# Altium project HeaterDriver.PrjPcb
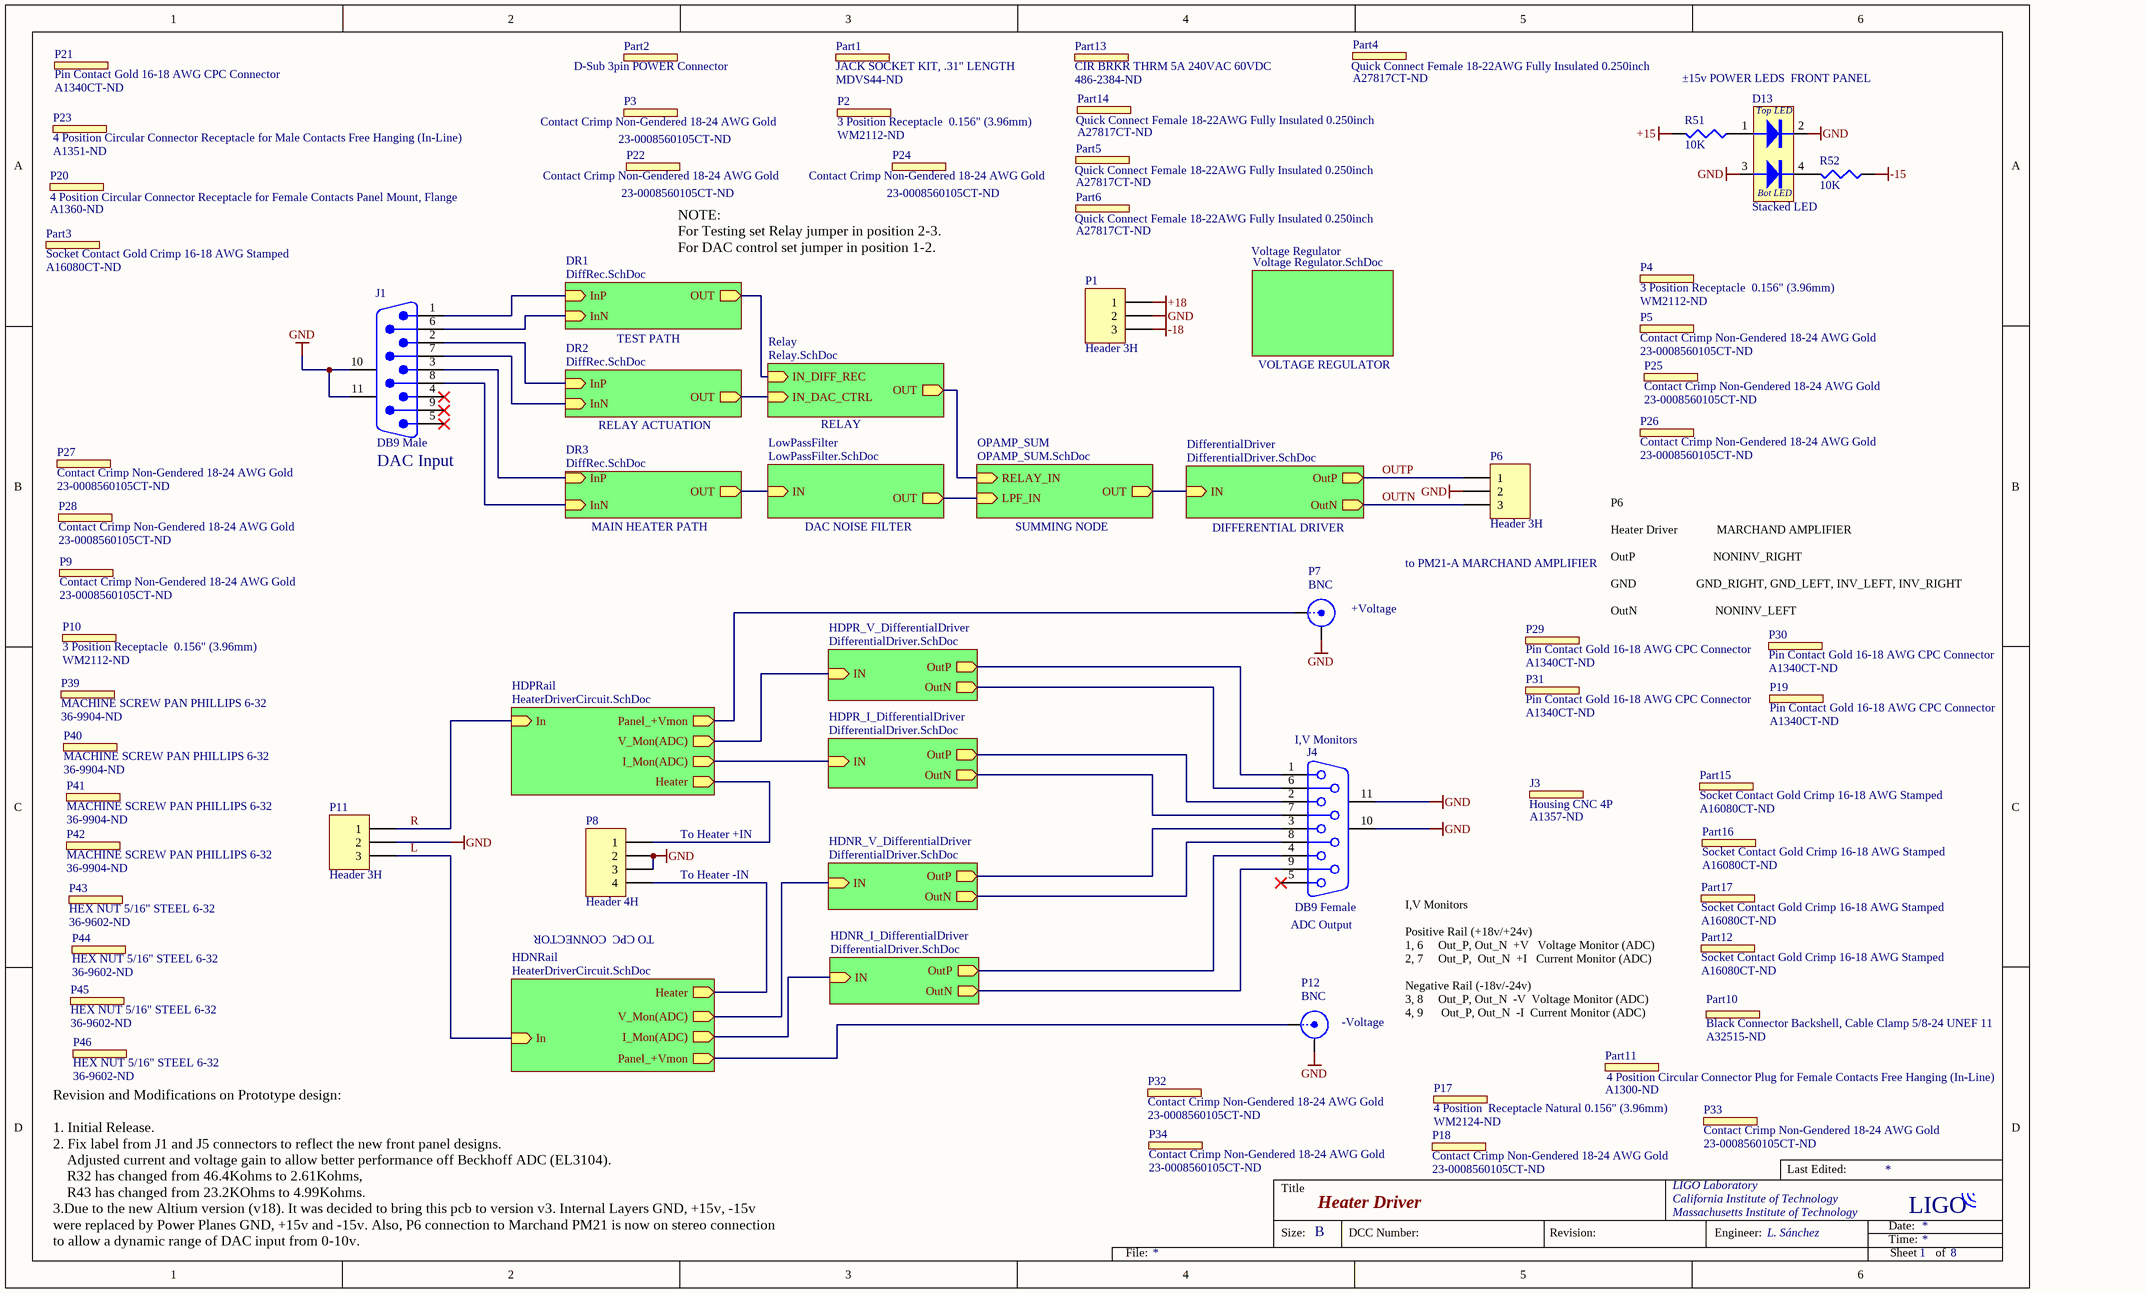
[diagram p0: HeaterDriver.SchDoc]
DCC: D1600454; REV: 3
8 sheets, 332 parts. Net scope: hierarchical (ports join the sheet entries above them; power ports are global).
Board file: HeaterContollerDriver.PcbDoc
Sheets:
  HeaterDriver.SchDoc
    Relay = Relay.SchDoc
    OPAMP_SUM = OPAMP_SUM.SchDoc
    LowPassFilter = LowPassFilter.SchDoc
    DR1 = DiffRec.SchDoc
    DR2 = DiffRec.SchDoc
    DR3 = DiffRec.SchDoc
    HDNR_I_DifferentialDriver = DifferentialDriver.SchDoc
    HDNR_V_DifferentialDriver = DifferentialDriver.SchDoc
    Voltage Regulator = Voltage Regulator.SchDoc
    HDPRail = HeaterDriverCircuit.SchDoc
    HDNRail = HeaterDriverCircuit.SchDoc
    DifferentialDriver = DifferentialDriver.SchDoc
    HDPR_V_DifferentialDriver = DifferentialDriver.SchDoc
    HDPR_I_DifferentialDriver = DifferentialDriver.SchDoc

## Sheet HeaterDriver.SchDoc: Heater Driver
size B; Organization: LIGO Laboratory; Address1: California Institute of Technology; Address2: Massachusetts Institute of Technology; DocumentNumber: D1600454; Revision: 3; SheetNumber: 1; SheetTotal: 8; Engineer: L. Sánchez

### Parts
D13  Stacked LED  [my LUMEX Dual LED]
J1  DB9 Male  [DB9M-RA]
J3  Housing CNC 4P  Digikey Part Number: A1357-ND  (mechanical)
J4  DB9 Female  [DB9F-RA]
P1  Header 3H  [Molex_156_RA_3]
P2  3 Position Receptacle  0.156" (3.96mm)  Digikey Part Number: WM2112-ND  (mechanical)
P3  Contact Crimp Non-Gendered 18-24 AWG Gold  Digikey Part Number: 23-0008560105CT-ND  (mechanical)
P4  3 Position Receptacle  0.156" (3.96mm)  Digikey Part Number: WM2112-ND  (mechanical)
P5  Contact Crimp Non-Gendered 18-24 AWG Gold  Digikey Part Number: 23-0008560105CT-ND  (mechanical)
P6  Header 3H  [Molex_156_RA_3]
P7  BNC  [BNC4]
P8  Header 4H  [Molex_156_RA_4]
P9  Contact Crimp Non-Gendered 18-24 AWG Gold  Digikey Part Number: 23-0008560105CT-ND  (mechanical)
P10  3 Position Receptacle  0.156" (3.96mm)  Digikey Part Number: WM2112-ND  (mechanical)
P11  Header 3H  [Molex_156_RA_3]
P12  BNC  [BNC4]
P17  4 Position  Receptacle Natural 0.156" (3.96mm)  Digikey Part Number: WM2124-ND  (mechanical)
P18  Contact Crimp Non-Gendered 18-24 AWG Gold  Digikey Part Number: 23-0008560105CT-ND  (mechanical)
P19  Pin Contact Gold 16-18 AWG CPC Connector  Digikey Part Number: A1340CT-ND  (mechanical)
P20  4 Position Circular Connector Receptacle for Female Contacts Panel Mount, Flange  Digikey Part Number: A1360-ND  (mechanical)
P21  Pin Contact Gold 16-18 AWG CPC Connector  Digikey Part Number: A1340CT-ND  (mechanical)
P22  Contact Crimp Non-Gendered 18-24 AWG Gold  Digikey Part Number: 23-0008560105CT-ND  (mechanical)
P23  4 Position Circular Connector Receptacle for Male Contacts Free Hanging (In-Line)  Digikey Part Number: A1351-ND  (mechanical)
P24  Contact Crimp Non-Gendered 18-24 AWG Gold  Digikey Part Number: 23-0008560105CT-ND  (mechanical)
P25  Contact Crimp Non-Gendered 18-24 AWG Gold  Digikey Part Number: 23-0008560105CT-ND  (mechanical)
P26  Contact Crimp Non-Gendered 18-24 AWG Gold  Digikey Part Number: 23-0008560105CT-ND  (mechanical)
P27  Contact Crimp Non-Gendered 18-24 AWG Gold  Digikey Part Number: 23-0008560105CT-ND  (mechanical)
P28  Contact Crimp Non-Gendered 18-24 AWG Gold  Digikey Part Number: 23-0008560105CT-ND  (mechanical)
P29  Pin Contact Gold 16-18 AWG CPC Connector  Digikey Part Number: A1340CT-ND  (mechanical)
P30  Pin Contact Gold 16-18 AWG CPC Connector  Digikey Part Number: A1340CT-ND  (mechanical)
P31  Pin Contact Gold 16-18 AWG CPC Connector  Digikey Part Number: A1340CT-ND  (mechanical)
P32  Contact Crimp Non-Gendered 18-24 AWG Gold  Digikey Part Number: 23-0008560105CT-ND  (mechanical)
P33  Contact Crimp Non-Gendered 18-24 AWG Gold  Digikey Part Number: 23-0008560105CT-ND  (mechanical)
P34  Contact Crimp Non-Gendered 18-24 AWG Gold  Digikey Part Number: 23-0008560105CT-ND  (mechanical)
P39  MACHINE SCREW PAN PHILLIPS 6-32  Digikey Part Number: 36-9904-ND  (mechanical)
P40  MACHINE SCREW PAN PHILLIPS 6-32  Digikey Part Number: 36-9904-ND  (mechanical)
P41  MACHINE SCREW PAN PHILLIPS 6-32  Digikey Part Number: 36-9904-ND  (mechanical)
P42  MACHINE SCREW PAN PHILLIPS 6-32  Digikey Part Number: 36-9904-ND  (mechanical)
P43  HEX NUT 5/16" STEEL 6-32  Digikey Part Number: 36-9602-ND  (mechanical)
P44  HEX NUT 5/16" STEEL 6-32  Digikey Part Number: 36-9602-ND  (mechanical)
P45  HEX NUT 5/16" STEEL 6-32  Digikey Part Number: 36-9602-ND  (mechanical)
P46  HEX NUT 5/16" STEEL 6-32  Digikey Part Number: 36-9602-ND  (mechanical)
Part1  JACK SOCKET KIT, .31" LENGTH  Digikey Part Number: MDVS44-ND  (mechanical)
Part2  D-Sub 3pin POWER Connector  (mechanical)
Part3  Socket Contact Gold Crimp 16-18 AWG Stamped  Digikey Part Number: A16080CT-ND  (mechanical)
Part4  Quick Connect Female 18-22AWG Fully Insulated 0.250inch  Digikey Part Number: A27817CT-ND  (mechanical)
Part5  Quick Connect Female 18-22AWG Fully Insulated 0.250inch  Digikey Part Number: A27817CT-ND  (mechanical)
Part6  Quick Connect Female 18-22AWG Fully Insulated 0.250inch  Digikey Part Number: A27817CT-ND  (mechanical)
Part10  Black Connector Backshell, Cable Clamp 5/8-24 UNEF 11  Digikey Part Number: A32515-ND  (mechanical)
Part11  4 Position Circular Connector Plug for Female Contacts Free Hanging (In-Line)  Digikey Part Number: A1300-ND  (mechanical)
Part12  Socket Contact Gold Crimp 16-18 AWG Stamped  Digikey Part Number: A16080CT-ND  (mechanical)
Part13  CIR BRKR THRM 5A 240VAC 60VDC  Digikey Part Number: 486-2384-ND  (mechanical)
Part14  Quick Connect Female 18-22AWG Fully Insulated 0.250inch  Digikey Part Number: A27817CT-ND  (mechanical)
Part15  Socket Contact Gold Crimp 16-18 AWG Stamped  Digikey Part Number: A16080CT-ND  (mechanical)
Part16  Socket Contact Gold Crimp 16-18 AWG Stamped  Digikey Part Number: A16080CT-ND  (mechanical)
Part17  Socket Contact Gold Crimp 16-18 AWG Stamped  Digikey Part Number: A16080CT-ND  (mechanical)
R51  value 10K  [CR3216-1206]  (hidden comment: 10K Resistor 1206 0.25W 0.1%)
R52  value 10K  [CR3216-1206]  (hidden comment: 10K Resistor 1206 0.25W 0.1%)

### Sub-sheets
DifferentialDriver = DifferentialDriver.SchDoc: IN (in), OutN (out), OutP (out)
DR1 = DiffRec.SchDoc: InP (in), InN (in), OUT (out)
DR2 = DiffRec.SchDoc: InP (in), InN (in), OUT (out)
DR3 = DiffRec.SchDoc: InP (in), InN (in), OUT (out)
HDNR_I_DifferentialDriver = DifferentialDriver.SchDoc: IN (in), OutN (out), OutP (out)
HDNR_V_DifferentialDriver = DifferentialDriver.SchDoc: IN (in), OutN (out), OutP (out)
HDNRail = HeaterDriverCircuit.SchDoc: In (in), I_Mon(ADC) (out), Heater (out), Panel_+Vmon (out), V_Mon(ADC) (out)
HDPR_I_DifferentialDriver = DifferentialDriver.SchDoc: IN (in), OutN (out), OutP (out)
HDPR_V_DifferentialDriver = DifferentialDriver.SchDoc: IN (in), OutN (out), OutP (out)
HDPRail = HeaterDriverCircuit.SchDoc: In (in), I_Mon(ADC) (out), Heater (out), Panel_+Vmon (out), V_Mon(ADC) (out)
LowPassFilter = LowPassFilter.SchDoc: IN (in), OUT (out)
OPAMP_SUM = OPAMP_SUM.SchDoc: RELAY_IN (in), LPF_IN (in), OUT (out)
Relay = Relay.SchDoc: IN_DAC_CTRL (in), IN_DIFF_REC (in), OUT (out)
Voltage Regulator = Voltage Regulator.SchDoc: no entries

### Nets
+15: R51.2
+18: P1.1
-15: R52.1
-18: P1.3
GND: D13.2(CATHODE) D13.3(ANODE) J1.10(MH1) J1.11(MH2) J4.10(MH1) J4.11(MH2) P1.2 P6.2 P7.2(Y) P8.2 P8.3 P11.2 P12.2(Y)
L: P11.3 ; sheet HDNRail/In
OUTN: P6.3 ; sheet DifferentialDriver/OutN
OUTP: P6.1 ; sheet DifferentialDriver/OutP
R: P11.1 ; sheet HDPRail/In
NetC5_1: sheet OPAMP_SUM/LPF_IN, sheet LowPassFilter/OUT
NetC19_HDNRail_2: sheet HDNR_V_DifferentialDriver/IN, sheet HDNRail/V_Mon(ADC)
NetC19_HDPRail_2: sheet HDPRail/V_Mon(ADC), sheet HDPR_V_DifferentialDriver/IN
NetD13_1: D13.1(COM) R51.1
NetD13_4: D13.4(ANODE) R52.2
NetF3_HDNRail_1: P8.4 ; sheet HDNRail/Heater
NetF3_HDPRail_1: P8.1 ; sheet HDPRail/Heater
NetH1_1: sheet Relay/IN_DAC_CTRL, sheet DR2/OUT
NetJ1_1: J1.1 ; sheet DR1/InP
NetJ1_2: J1.2 ; sheet DR2/InP
NetJ1_3: J1.3 ; sheet DR3/InP
NetJ1_6: J1.6 ; sheet DR1/InN
NetJ1_7: J1.7 ; sheet DR2/InN
NetJ1_8: J1.8 ; sheet DR3/InN
NetJ4_1: J4.1 ; sheet HDPR_V_DifferentialDriver/OutP
NetJ4_2: J4.2 ; sheet HDPR_I_DifferentialDriver/OutP
NetJ4_3: J4.3 ; sheet HDNR_V_DifferentialDriver/OutP
NetJ4_4: J4.4 ; sheet HDNR_I_DifferentialDriver/OutP
NetJ4_6: J4.6 ; sheet HDPR_V_DifferentialDriver/OutN
NetJ4_7: J4.7 ; sheet HDPR_I_DifferentialDriver/OutN
NetJ4_8: J4.8 ; sheet HDNR_V_DifferentialDriver/OutN
NetJ4_9: J4.9 ; sheet HDNR_I_DifferentialDriver/OutN
NetP7_1: P7.1(X) ; sheet HDPRail/Panel_+Vmon
NetP12_1: P12.1(X) ; sheet HDNRail/Panel_+Vmon
NetR9_DR1_1: sheet Relay/IN_DIFF_REC, sheet DR1/OUT
NetR9_DR3_1: sheet LowPassFilter/IN, sheet DR3/OUT
NetR16_1: sheet Relay/OUT, sheet OPAMP_SUM/RELAY_IN
NetR23_2: sheet OPAMP_SUM/OUT, sheet DifferentialDriver/IN
NetR27_HDNR_I_DifferentialDriver_1: sheet HDNR_I_DifferentialDriver/IN, sheet HDNRail/I_Mon(ADC)
NetR27_HDPR_I_DifferentialDriver_1: sheet HDPRail/I_Mon(ADC), sheet HDPR_I_DifferentialDriver/IN

Not connected (* = marked no-connect by the designer): J1 4* 5* 9*; J4 5*

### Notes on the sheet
- ±15v POWER LEDS  FRONT PANEL
- NOTE:
  For Testing set Relay jumper in position 2-3.
  For DAC control set jumper in position 1-2.
- TEST PATH
- VOLTAGE REGULATOR
- RELAY ACTUATION
- RELAY
- (near J1) DAC Input
- MAIN HEATER PATH
- DAC NOISE FILTER
- SUMMING NODE
- DIFFERENTIAL DRIVER
- to PM21-A MARCHAND AMPLIFIER
- (near P7) +Voltage
- (near P30) P6
  Heater Driver             MARCHAND AMPLIFIER
  OutP                          NONINV_RIGHT
  GND                    GND_RIGHT, GND_LEFT, INV_LEFT, INV_RIGHT
  OutN                          NONINV_LEFT
- To Heater +IN
- To Heater -IN
- (near P8) TO CPC  CONNECTOR
- (near P12) -Voltage
- I,V Monitors
  Positive Rail (+18v/+24v)
  1, 6     Out_P, Out_N  +V   Voltage Monitor (ADC)
  2, 7     Out_P,  Out_N  +I   Current Monitor (ADC)
  Negative Rail (-18v/-24v)
  3, 8     Out_P, Out_N  -V  Voltage Monitor (ADC)
  4, 9      Out_P, Out_N  -I  Current Monitor (ADC)
- (near P46) Revision and Modifications on Prototype design:
  1. Initial Release.
  2. Fix label from J1 and J5 connectors to reflect the new front panel designs.
  Adjusted current and voltage gain to allow better performance off Beckhoff ADC (EL3104).
  R32 has changed from 46.4Kohms to 2.61Kohms,
  R43 has changed from 23.2KOhms to 4.99Kohms.
  3.Due to the new Altium version (v18). It was decided to bring this pcb to version v3. Internal Layers GND, +15v, -15v were replaced by Power Planes GND, +15v and -15v. Also, P6 connection to Marchand PM21 is now on stereo connection to allow a dynamic range of DAC input from 0-10v.

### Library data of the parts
D13 = Dual Stacked LED: Dual Green LED
J1 = DB9M: Plug Assembly, 9 Position, Right Angle, .318 Series; Value: 6E17C-009P-AJ-121-ND
J3 = Mechanical Part: Manufacturers Part Number: 206429-1; Value: A1357-ND
J4 = D Connector 9: Receptacle Assembly, 9 Position, Right Angle; Manufacturers Part Number: 5747844-4; Value: A32117-ND
P1 P6 P11 = Header 3H: Header, 3-Pin, Right Angle
P2 P4 P10 = Mechanical Part: Manufacturers Part Number: 0009508033; Value: WM2112-ND
P3 P5 P9 P18 P22 P24-P28 P32-P34 = Mechanical Part: Value: 0008560106
P7 P12 = BNC: BNC Straight Away Connector; Manufacturers Part Number: 5227161-7; Value: A144890-ND
P8 = Header 4H: Header, 4-Pin, Right Angle
P17 = Mechanical Part: Manufacturers Part Number: 0009508041
P19 P21 P29-P31 = Mechanical Part: Manufacturers Part Number: 66098-9; Value: A1340CT-ND
P20 = Mechanical Part: Manufacturers Part Number: 206430-1
P23 = Mechanical Part: Manufacturers Part Number: 206153-1
P39-P42 = Mechanical Part: Manufacturers Part Number: 9904
P43-P46 = Mechanical Part: Manufacturers Part Number: 9602
Part1 = Mechanical Part: Manufacturers Part Number: 3341-1S; Value: 523-17-D20418-2-TX
Part2 = Mechanical Part: Value: 3003W3PXX42A10X
Part3 Part12 Part15-Part17 = Mechanical Part: Manufacturers Part Number: 66100-9
Part4-Part6 Part14 = Mechanical Part: Manufacturers Part Number: 2-520183-2
Part10 = Mechanical Part: Manufacturers Part Number: 1-206062-4
Part11 = Mechanical Part: Manufacturers Part Number: 206060-1
Part13 = Mechanical Part: Manufacturers Part Number: 4435.0039
R51 R52 = 1206_Res_10K: SMD 1206 Resistor 10K 0.25W 0.1%; Manufacturers Part Number: RNCP1206FTD10K0

## Sheet Relay.SchDoc: Relay
size A; Organization: LIGO Laboratory; Address1: California Institute of Technology; Address2: Massachusetts Institute of Technology; DocumentNumber: D1600454; Revision: 3; SheetNumber: 3; SheetTotal: 8; Engineer: L.Sánchez
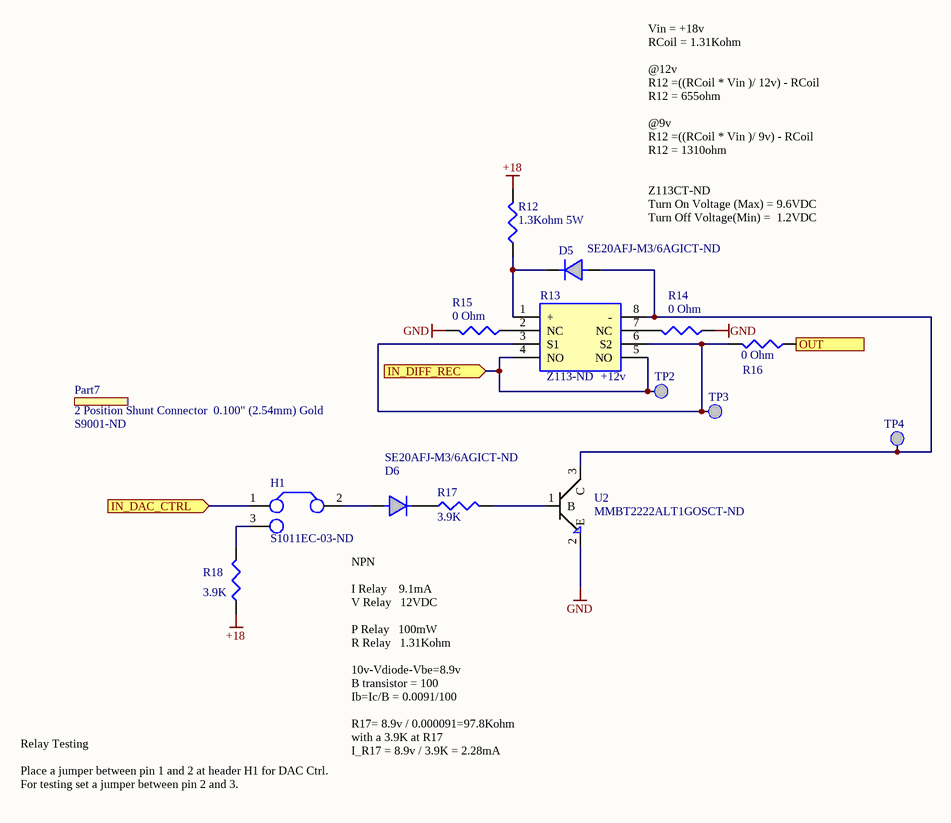
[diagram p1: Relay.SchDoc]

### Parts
D5  Supplier Part Number 1: SE20AFJ-M3/6AGICT-ND  [DIODE_SE20AFJ-M3/6A]  (hidden comment: Diode General)
D6  Supplier Part Number 1: SE20AFJ-M3/6AGICT-ND  [DIODE_SE20AFJ-M3/6A]  (hidden comment: Diode General)
H1  Digikey Part Number: S1011EC-03-ND  [Jumper 3P]  (hidden comment: Header 3P Gold Unshrouded 0.100inch)
Part7  2 Position Shunt Connector  0.100" (2.54mm) Gold  Digikey Part Number: S9001-ND  (mechanical)
R12  value 1.3Kohm 5W  [Axial_Res_925]  (hidden comment: Res 1.3Kohm, 5W,5% Axial)
R13  Digikey Part Number: Z113-ND  [RELAY_G6K-2F-TR-DC5]  (hidden comment: Relay DPDT SMD 12v DC)
R14  0 Ohm  [CR3216-1206]
R15  0 Ohm  [CR3216-1206]
R16  0 Ohm  [CR3216-1206]
R17  value 3.9K  [CR3216-1206]  (hidden comment: SMD Res 3.9K 0.1% 0.25W 1206)
R18  value 3.9K  [CR3216-1206]  (hidden comment: SMD Res 3.9K 0.1% 0.25W 1206)
TP2  TESTPT  [TP3heater]  (value not drawn)
TP3  TESTPT  [TP3heater]  (value not drawn)
TP4  TESTPT  [TP3heater]  (value not drawn)
U2  Supplier Part Number 1: MMBT2222ALT1GOSCT-ND  [SOT-23-3]  (hidden comment: Transistor Switch NPN General Purpose 40v 1Amp)

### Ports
IN_DAC_CTRL (in), IN_DIFF_REC (in), OUT (out)

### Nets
+18: R12.2 R18.1
GND: R14.1 R15.2 U2.2(E)
NetD5_1: D5.1(K) R12.1 R13.1(+)
NetD5_2: D5.2(A) R13.8(-) TP4.1 U2.3(C)
NetD6_1: D6.1(K) R17.1
NetD6_2: D6.2(A) H1.2
NetH1_1: H1.1 ; port IN_DAC_CTRL
NetH1_3: H1.3 R18.2
NetR9_DR1_1: R13.4(NO) R13.5(NO) TP2.1 ; port IN_DIFF_REC
NetR13_2: R13.2(NC) R15.1
NetR13_3: R13.3(S1) R13.6(S2) R16.2 TP3.1
NetR13_7: R13.7(NC) R14.2
NetR16_1: R16.1 ; port OUT
NetR17_2: R17.2 U2.1(B)

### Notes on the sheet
- Vin = +18v
  RCoil = 1.31Kohm
  @12v
  R12 =((RCoil * Vin )/ 12v) - RCoil
  R12 = 655ohm
  @9v
  R12 =((RCoil * Vin )/ 9v) - RCoil
  R12 = 1310ohm
  Z113CT-ND
  Turn On Voltage (Max) = 9.6VDC
  Turn Off Voltage(Min) =  1.2VDC
- NPN
  I Relay    9.1mA
  V Relay   12VDC
  P Relay   100mW
  R Relay   1.31Kohm
  10v-Vdiode-Vbe=8.9v
  B transistor = 100
  Ib=Ic/B = 0.0091/100
  R17= 8.9v / 0.000091=97.8Kohm
  with a 3.9K at R17
  I_R17 = 8.9v / 3.9K = 2.28mA
- Relay Testing
  Place a jumper between pin 1 and 2 at header H1 for DAC Ctrl.
  For testing set a jumper between pin 2 and 3.

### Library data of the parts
D5 D6 = DIODE_SE20AFJ-M3/6A: Value: SE20AFJ-M3/6AGICT-ND
H1 = Header_3P: Manufacturers Part Number: PRPC003SAAN-RC; Value: S1011EC-03-ND
Part7 = Mechanical Part: 2 (1 x 2) Position Shunt Connector Black Closed Top 0.100" (2.54mm) Gold; Manufacturers Part Number: SPC02SYAN; Value: S9001-ND
R12 = Axial_TH_Res_1.30K_5W: Manufacturers Part Number: SQP500JB-1K3; Tolerance: 0.1%
R13 = RELAY_G6K-2F-TR-DC12: Manufacturers Part Number: G6K-2F DC12; Tolerance: 0.1%
R14-R16 = Res3: Resistor; Tolerance: 0.1%
R17 R18 = 1206_Res_3.9K: Manufacturers Part Number: ERA-8AEB392V
TP2-TP4 = TESTPT: PCB Testpoint; 'Manufacturers Part Number: 5016; Value: 36-5016CT-ND
U2 = MMBT2222A_NPN

## Sheet OPAMP_SUM.SchDoc: OP AMP SUM
size A; Organization: LIGO Laboratory; Address1: California Institute of Technology; Address2: Massachusetts Institute of Technology; DocumentNumber: D1600454; Revision: 3; SheetNumber: 5; SheetTotal: 8; Engineer: L.Sánchez
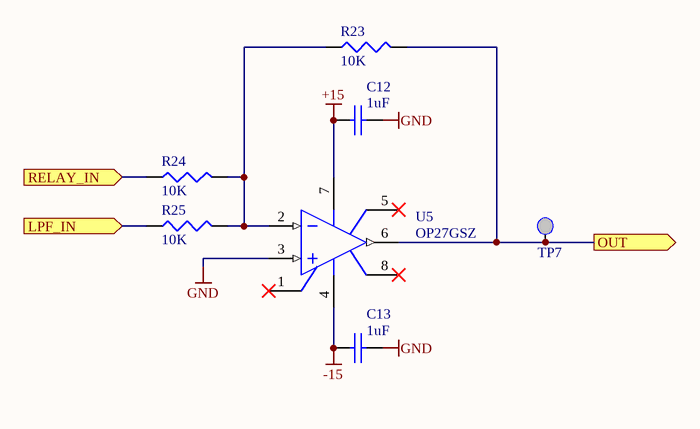
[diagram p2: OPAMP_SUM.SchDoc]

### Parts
C12  1uF  [CC3216-1206]
C13  1uF  [CC3216-1206]
R23  value 10K  [CR3216-1206]  (hidden comment: 10K Resistor 1206 0.25W 0.1%)
R24  value 10K  [CR3216-1206]  (hidden comment: 10K Resistor 1206 0.25W 0.1%)
R25  value 10K  [CR3216-1206]  (hidden comment: 10K Resistor 1206 0.25W 0.1%)
TP7  TESTPT  [TP3heater]  (value not drawn)
U5  OP27GSZ  [SO8_N]

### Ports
LPF_IN (in), OUT (out), RELAY_IN (in)

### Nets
+15: C12.1 U5.7(V+)
-15: C13.1 U5.4(V-)
GND: C12.2 C13.2 U5.3(IN+)
NetC5_1: R25.1 ; port LPF_IN
NetR16_1: R24.1 ; port RELAY_IN
NetR23_1: R23.1 R24.2 R25.2 U5.2(IN-)
NetR23_2: R23.2 TP7.1 U5.6(OUT) ; port OUT

Not connected (* = marked no-connect by the designer): U5 1(NULL1)* 5(NC)* 8(NULL2)*

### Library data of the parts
C12 C13 = MYCAP: CAP 1.0UF 50V CERAMIC F 1206; Tolerance: 5%
R23-R25 = 1206_Res_10K: as R51 on sheet HeaterDriver
TP7 = TESTPT: as TP2 on sheet Relay
U5 = ADOP27AQ: Ultra-Low Noise, Precision Operational Amplifier; Value: OP27GSZ-ND

## Sheet LowPassFilter.SchDoc: Low Pass Filter
size A; Organization: LIGO Laboratory; Address1: California Institute of Technology; Address2: Massachusetts Institute of Technology; DocumentNumber: D1600454; Revision: 3; SheetNumber: 4; SheetTotal: 8; Engineer: L.Sánchez
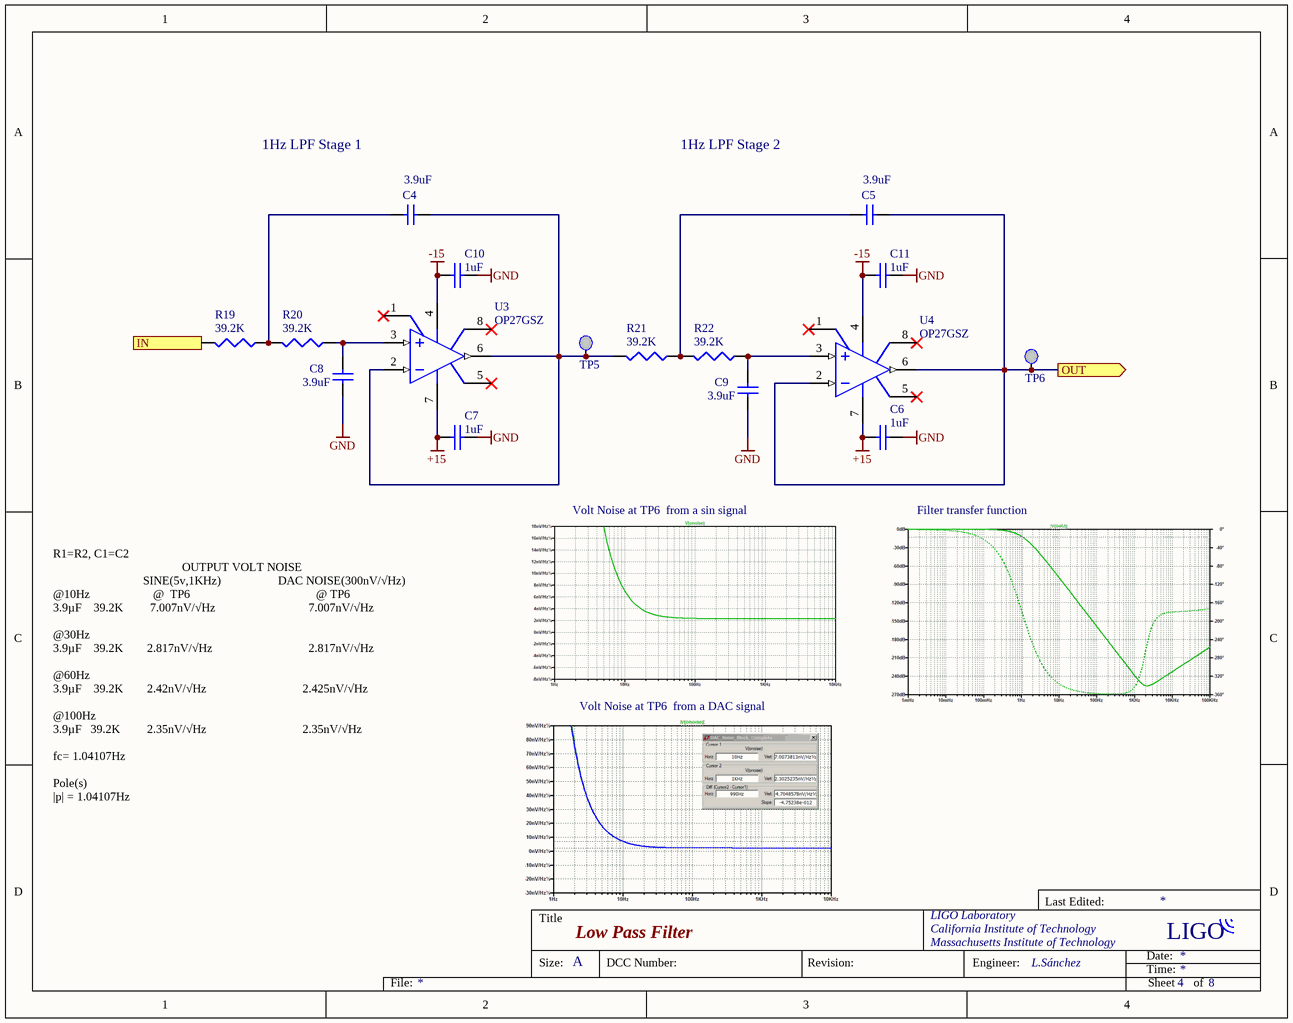
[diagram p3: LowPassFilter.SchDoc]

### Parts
C4  value 3.9uF  [CAP_FILM_0.689inch]  (hidden comment: Cap Film 3.9uF 250v 10%)
C5  value 3.9uF  [CAP_FILM_0.689inch]  (hidden comment: Cap Film 3.9uF 250v 10%)
C6  1uF  [CC3216-1206]
C7  1uF  [CC3216-1206]
C8  value 3.9uF  [CAP_FILM_0.689inch]  (hidden comment: Cap Film 3.9uF 250v 10%)
C9  value 3.9uF  [CAP_FILM_0.689inch]  (hidden comment: Cap Film 3.9uF 250v 10%)
C10  1uF  [CC3216-1206]
C11  1uF  [CC3216-1206]
R19  39.2K  [CR3216-1206]
R20  39.2K  [CR3216-1206]
R21  39.2K  [CR3216-1206]
R22  39.2K  [CR3216-1206]
TP5  TESTPT  [TP3heater]  (value not drawn)
TP6  TESTPT  [TP3heater]  (value not drawn)
U3  OP27GSZ  [SO8_N]
U4  OP27GSZ  [SO8_N]

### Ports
IN (in), OUT (out)

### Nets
+15: C6.1 C7.1 U3.7(V+) U4.7(V+)
-15: C10.1 C11.1 U3.4(V-) U4.4(V-)
GND: C6.2 C7.2 C8.1 C9.1 C10.2 C11.2
NetC4_1: C4.1 R21.2 TP5.1 U3.2(IN-) U3.6(OUT)
NetC4_2: C4.2 R19.1 R20.2
NetC5_1: C5.1 TP6.1 U4.2(IN-) U4.6(OUT) ; port OUT
NetC5_2: C5.2 R21.1 R22.2
NetC8_2: C8.2 R20.1 U3.3(IN+)
NetC9_2: C9.2 R22.1 U4.3(IN+)
NetR9_DR3_1: R19.2 ; port IN

Not connected (* = marked no-connect by the designer): U3 1(NULL1)* 5(NC)* 8(NULL2)*; U4 1(NULL1)* 5(NC)* 8(NULL2)*

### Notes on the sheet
- 1Hz LPF Stage 1
- 1Hz LPF Stage 2
- Volt Noise at TP6  from a sin signal
- Filter transfer function
- Volt Noise at TP6  from a DAC signal
- R1=R2, C1=C2
  OUTPUT VOLT NOISE
  SINE(5v,1KHz)                   DAC NOISE(300nV/√Hz)
  @10Hz                     @  TP6                                          @ TP6
  3.9µF    39.2K         7.007nV/√Hz                               7.007nV/√Hz
  @30Hz
  3.9µF    39.2K        2.817nV/√Hz                                2.817nV/√Hz
  @60Hz
  3.9µF    39.2K        2.42nV/√Hz                                2.425nV/√Hz
  @100Hz
  3.9µF   39.2K         2.35nV/√Hz                                2.35nV/√Hz
  fc= 1.04107Hz
  Pole(s)
  |p| = 1.04107Hz

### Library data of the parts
C4 C5 C8 C9 = CAP_Radial_3.9uF_250v: Manufacturers Part Number: ECQ-E2395JB; Tolerance: 3%
C6 C7 C10 C11 = MYCAP: as C12 on sheet OPAMP_SUM
R19-R22 = MYRES: 39.2K Film Resistor; 'Manufacturers Part Number: ERA-8AEB3922V; Tolerance: 0.1%
TP5 TP6 = TESTPT: as TP2 on sheet Relay
U3 U4 = ADOP27AQ: as U5 on sheet OPAMP_SUM

## Sheet DiffRec.SchDoc: Differential Receiver
size A; Organization: LIGO Laboratory; Address1: California Institute of Technology; Address2: Massachusetts Institute of Technology; DocumentNumber: D1600454; Revision: 3; SheetNumber: 2; SheetTotal: 8; Engineer: L.Sanchez
Used 3 times, as channels DR1, DR2, DR3. Parts and nets are listed once, with the designators drawn on the sheet.
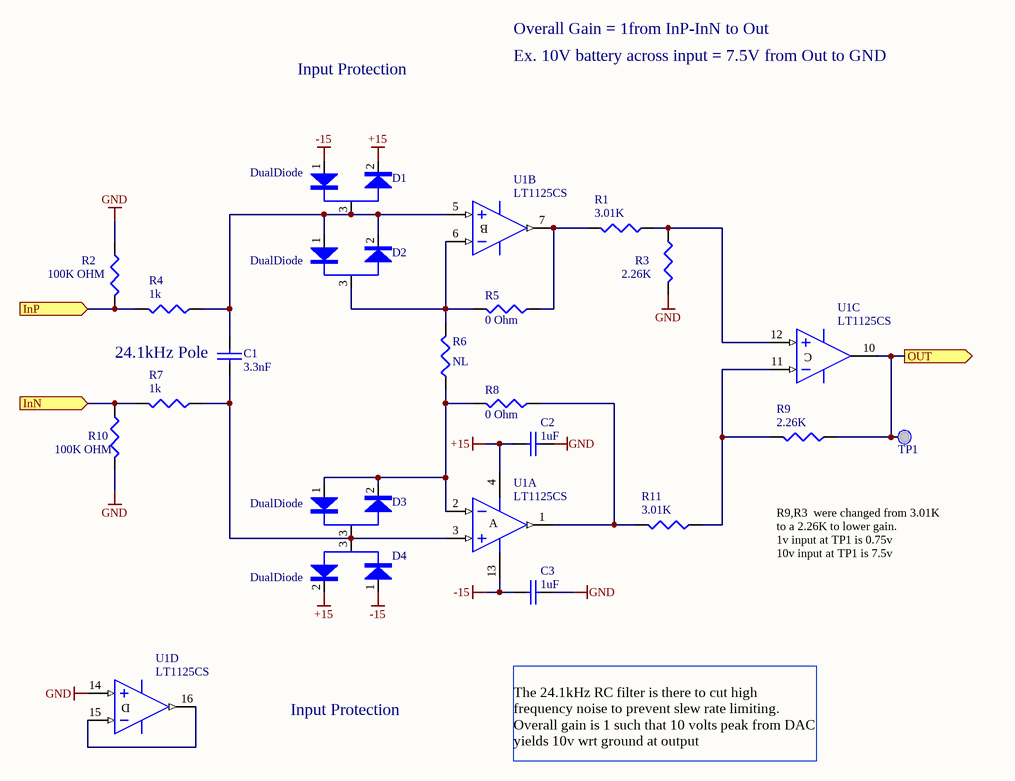
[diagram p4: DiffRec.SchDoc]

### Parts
C1  3.3nF  [CC3216-1206]
C2  1uF  [CC3216-1206]
C3  1uF  [CC3216-1206]
D1  DualDiode  [SOT-23A]
D2  DualDiode  [SOT-23A]
D3  DualDiode  [SOT-23A]
D4  DualDiode  [SOT-23A]
R1  3.01K  [CR3216-1206]
R2  100K OHM  [CR3216-1206]
R3  value 2.26K  [CR3216-1206]  (hidden comment: RES SMD 2.26K OHM 0.1% 1/4W 1206)
R4  1k  [CR3216-1206]
R5  0 Ohm  [CR3216-1206]
R6  NL  [CR3216-1206]
R7  1k  [CR3216-1206]
R8  0 Ohm  [CR3216-1206]
R9  value 2.26K  [CR3216-1206]  (hidden comment: RES SMD 2.26K OHM 0.1% 1/4W 1206)
R10  100K OHM  [CR3216-1206]
R11  3.01K  [CR3216-1206]
TP1  TESTPT  [TP3heater]  (value not drawn)
U1  LT1125CS  [SOIC127P1030-16N]  (parts A,B,C,D of 4)

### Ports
InN (in), InP (in), OUT (out)

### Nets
+15: C2.1 D1.2(CATHODE) D4.2(CATHODE) U1.4(V+)
-15: C3.1 D1.1(ANODE) D4.1(ANODE) U1.13(V-)
GND: C2.2 C3.2 R2.1 R3.2 R10.2 U1.14(IN+)
InN: R7.2 R10.1 ; port InN
InP: R2.2 R4.2 ; port InP
OUT: R9.1 TP1.1 U1.10(OUT) ; port OUT
NetC1_1: C1.1 D3.3(COM) D4.3(COM) R7.1 U1.3(IN+)
NetC1_2: C1.2 D1.3(COM) D2.1(ANODE) D2.2(CATHODE) R4.1 U1.5(IN+)
NetD2_3: D2.3(COM) R5.2 R6.2 U1.6(IN-)
NetD3_1: D3.1(ANODE) D3.2(CATHODE) R6.1 R8.2 U1.2(IN-)
NetR1_1: R1.1 R3.1 U1.12(IN+)
NetR1_2: R1.2 R5.1 U1.7(OUT)
NetR8_1: R8.1 R11.2 U1.1(OUT)
NetR9_2: R9.2 R11.1 U1.11(IN-)
NetU1_15: U1.15(IN-) U1.16(OUT)

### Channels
DR1: designators end in _DR1; ports InN=NetJ1_6 InP=NetJ1_1 OUT=NetR9_DR1_1
DR2: designators end in _DR2; ports InN=NetJ1_7 InP=NetJ1_2 OUT=NetH1_1
DR3: designators end in _DR3; ports InN=NetJ1_8 InP=NetJ1_3 OUT=NetR9_DR3_1

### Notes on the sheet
- Overall Gain = 1from InP-InN to Out
- Input Protection
- Ex. 10V battery across input = 7.5V from Out to GND
- (near C1) 24.1kHz Pole
- R9,R3  were changed from 3.01K to a 2.26K to lower gain.
  1v input at TP1 is 0.75v
  10v input at TP1 is 7.5v
- The 24.1kHz RC filter is there to cut high frequency noise to prevent slew rate limiting. Overall gain is 1 such that 10 volts peak from DAC yields 10v wrt ground at output

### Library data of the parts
C1 = MYCAP: CAP 3.3nF 50V PPS 1206; Manufacturers Part Number: ECH-U1H332GX5; Tolerance: 3%
C2 C3 = MYCAP: as C12 on sheet OPAMP_SUM
D1-D4 = DualDiode: DUAL SERIES DIODE.; Manufacturers Part Number: BAS70-04LT1G; Value: BAS70-04LT1GOSCT-ND
R1 R11 = MYRES: Resistor; 'Manufacturers Part Number: ERA-8AEB3011V; Tolerance: 0.1%
R2 R10 = MYRES: Resistor; 'Manufacturers Part Number: ERA-8AEB104V; Tolerance: 0.1%
R3 R9 = MYRES: 'Manufacturers Part Number: ERA-8AEB3011V; Manufacturers Part Number: ERA-8AEB2261V
R4 R7 = MYRES: Resistor; 'Manufacturers Part Number: ERA-8AEB102V; Tolerance: 0.1%
R5 R8 = Res3: Resistor; Tolerance: 0.1%
R6 = MYRES: Resistor; Tolerance: 0.1%
TP1 = TESTPT: as TP2 on sheet Relay
U1 = LT1125CS: Quad Low Noise, High-Speed Precision Operational Amplifier; 'Manufacturers Part Number: LT1125CSW#PBF

## Sheet DifferentialDriver.SchDoc: Differential Driver
size A; Organization: LIGO Laboratory; Address1: California Institute of Technology; Address2: Massachusetts Institute of Technology; DocumentNumber: D1600454; Revision: 3; SheetNumber: 6; SheetTotal: 8; Engineer: L.Sanchez
Used 5 times, as channels HDNR_I_DifferentialDriver, HDNR_V_DifferentialDriver, DifferentialDriver, HDPR_V_DifferentialDriver, HDPR_I_DifferentialDriver. Parts and nets are listed once, with the designators drawn on the sheet.
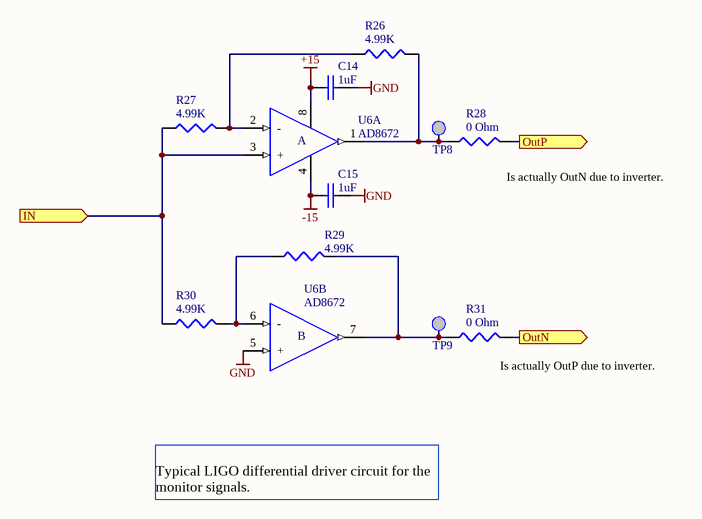
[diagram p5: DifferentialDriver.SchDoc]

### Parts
C14  1uF  [CC3216-1206]
C15  1uF  [CC3216-1206]
R26  4.99K  [CR3216-1206]
R27  4.99K  [CR3216-1206]
R28  0 Ohm  [CR3216-1206]
R29  4.99K  [CR3216-1206]
R30  4.99K  [CR3216-1206]
R31  0 Ohm  [CR3216-1206]
TP8  TESTPT  [TP3heater]  (value not drawn)
TP9  TESTPT  [TP3heater]  (value not drawn)
U6  AD8672  [SOIC_8P_]  (parts A,B of 2)

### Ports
IN (in), OutN (out), OutP (out)

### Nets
+15: C14.2 U6.8
-15: C15.2 U6.4
GND: C14.1 C15.1 U6.5(+)
IN: R27.1 R30.1 U6.3(+) ; port IN
OutN: R31.2 ; port OutN
OutP: R28.2 ; port OutP
NetR26_1: R26.1 R27.2 U6.2(-)
NetR26_2: R26.2 R28.1 TP8.1 U6.1
NetR29_1: R29.1 R30.2 U6.6(-)
NetR29_2: R29.2 R31.1 TP9.1 U6.7

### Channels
HDNR_I_DifferentialDriver: designators end in _HDNR_I_DifferentialDriver; ports IN=NetR27_HDNR_I_DifferentialDriver_1 OutN=NetJ4_9 OutP=NetJ4_4
HDNR_V_DifferentialDriver: designators end in _HDNR_V_DifferentialDriver; ports IN=NetC19_HDNRail_2 OutN=NetJ4_8 OutP=NetJ4_3
DifferentialDriver: designators end in _DifferentialDriver; ports IN=NetR23_2 OutN=OUTN OutP=OUTP
HDPR_V_DifferentialDriver: designators end in _HDPR_V_DifferentialDriver; ports IN=NetC19_HDPRail_2 OutN=NetJ4_6 OutP=NetJ4_1
HDPR_I_DifferentialDriver: designators end in _HDPR_I_DifferentialDriver; ports IN=NetR27_HDPR_I_DifferentialDriver_1 OutN=NetJ4_7 OutP=NetJ4_2

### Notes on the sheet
- (near R28) Is actually OutN due to inverter.
- (near R31) Is actually OutP due to inverter.
- Typical LIGO differential driver circuit for the monitor signals.

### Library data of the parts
C14 C15 = MYCAP: as C12 on sheet OPAMP_SUM
R26 R27 R29 R30 = Res3: Resistor; 'Manufacturers Part Number: TNPW12064K99BEEA; Tolerance: 0.1%
R28 R31 = Res3: Resistor; Tolerance: 0.1%
TP8 TP9 = TESTPT: as TP2 on sheet Relay
U6 = AD8672: High-Speed, Low-Power Dual Operational Amplifier; 'Manufacturers Part Number: AD8672ARZ-REEL7

## Sheet Voltage Regulator.SchDoc: Voltage Regulator
size A; Organization: LIGO Laboratory; Address1: California Institute of Technology; Address2: Massachusetts Institute of Technology; DocumentNumber: D1600454; Revision: 3; SheetNumber: 8; SheetTotal: 8; Engineer: L.Sánchez
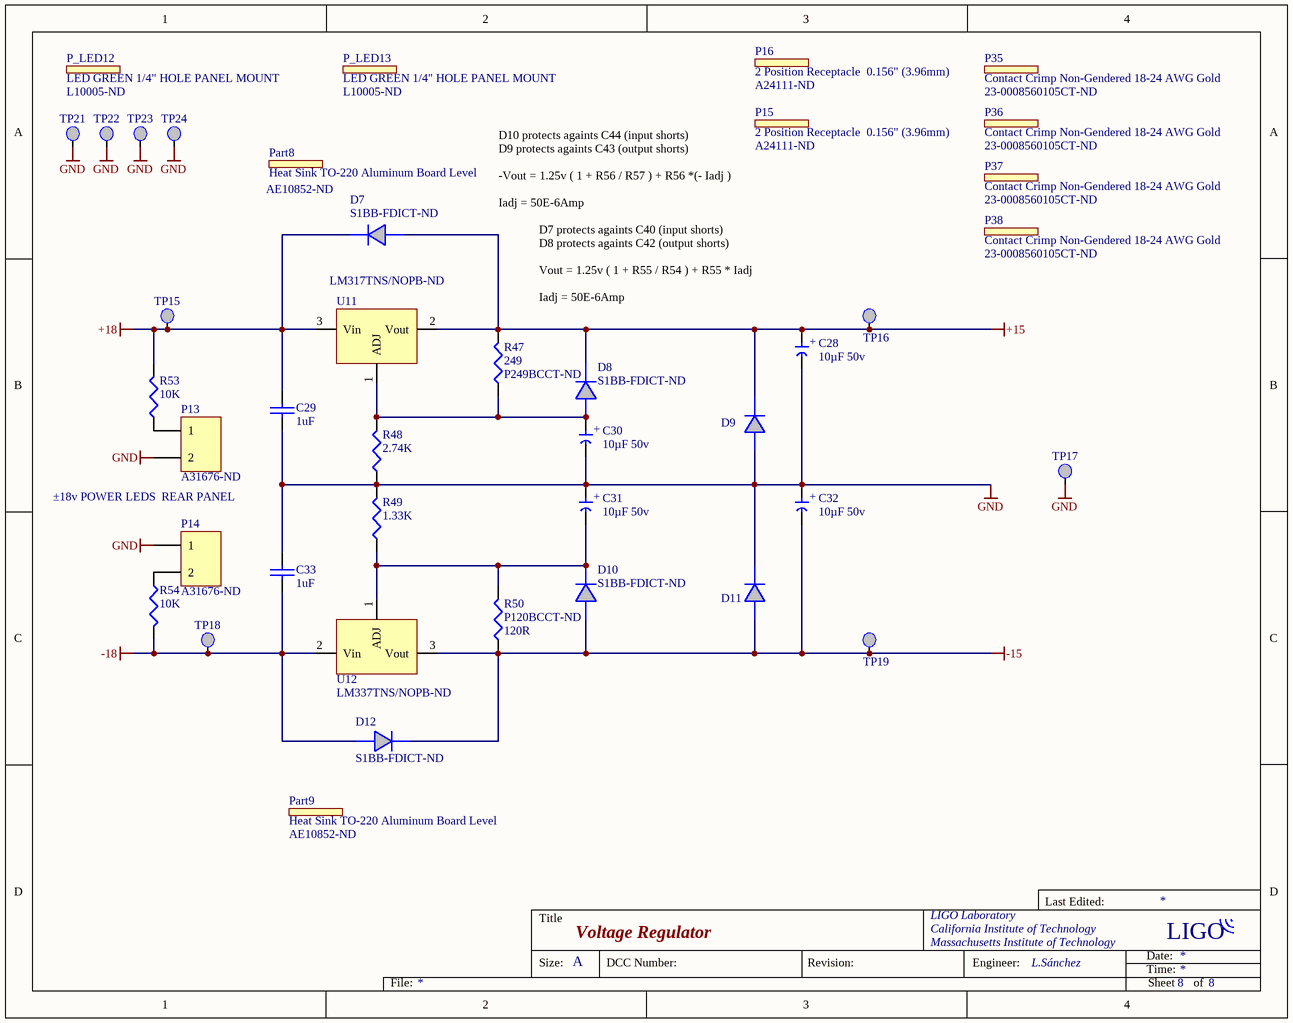
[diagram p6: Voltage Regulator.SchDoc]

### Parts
C28  value 10µF 50v  [2916]  (hidden comment: SMD Cap Tantalum Poly 10uF 50v 2917)
C29  1uF  [CC3216-1206]
C30  value 10µF 50v  [2916]  (hidden comment: SMD Cap Tantalum Poly 10uF 50v 2917)
C31  value 10µF 50v  [2916]  (hidden comment: SMD Cap Tantalum Poly 10uF 50v 2917)
C32  value 10µF 50v  [2916]  (hidden comment: SMD Cap Tantalum Poly 10uF 50v 2917)
C33  1uF  [CC3216-1206]
D7  Supplier Part Number 1: S1BB-FDICT-ND  [DIODE_SMB]  (hidden comment: Diode Standard 100V 1A Surface Mount SMB)
D8  Supplier Part Number 1: S1BB-FDICT-ND  [DIODE_SMB]  (hidden comment: Diode Standard 100V 1A Surface Mount SMB)
D9  Diode Schottky 60v 1A SMT PMDU SOD-123F  [SOD-123F]  (value not drawn)
D10  Supplier Part Number 1: S1BB-FDICT-ND  [DIODE_SMB]  (hidden comment: Diode Standard 100V 1A Surface Mount SMB)
D11  Diode Schottky 60v 1A SMT PMDU SOD-123F  [SOD-123F]  (value not drawn)
D12  Supplier Part Number 1: S1BB-FDICT-ND  [DIODE_SMB]  (hidden comment: Diode Standard 100V 1A Surface Mount SMB)
P13  Digikey Part Number: A31676-ND  [MOLEX_156_2]  (hidden comment: Header 2P 0.156inch Vertical)
P14  Digikey Part Number: A31676-ND  [MOLEX_156_2]  (hidden comment: Header 2P 0.156inch Vertical)
P15  2 Position Receptacle  0.156" (3.96mm)  Digikey Part Number: A24111-ND  (mechanical)
P16  2 Position Receptacle  0.156" (3.96mm)  Digikey Part Number: A24111-ND  (mechanical)
P35  Contact Crimp Non-Gendered 18-24 AWG Gold  Digikey Part Number: 23-0008560105CT-ND  (mechanical)
P36  Contact Crimp Non-Gendered 18-24 AWG Gold  Digikey Part Number: 23-0008560105CT-ND  (mechanical)
P37  Contact Crimp Non-Gendered 18-24 AWG Gold  Digikey Part Number: 23-0008560105CT-ND  (mechanical)
P38  Contact Crimp Non-Gendered 18-24 AWG Gold  Digikey Part Number: 23-0008560105CT-ND  (mechanical)
P_LED12  LED GREEN 1/4" HOLE PANEL MOUNT  Digikey Part Number: L10005-ND  (mechanical)
P_LED13  LED GREEN 1/4" HOLE PANEL MOUNT  Digikey Part Number: L10005-ND  (mechanical)
Part8  Heat Sink TO-220 Aluminum Board Level  Digikey Part Number: AE10852-ND  (mechanical)
Part9  Heat Sink TO-220 Aluminum Board Level  Digikey Part Number: AE10852-ND  (mechanical)
R47  value 249  Supplier Part Number 1: P249BCCT-ND  [CR3216-1206]  (hidden comment: SMD Res 249Ohm 0.1% 0.25W 1206)
R48  value 2.74K  [CR3216-1206]  (hidden comment: SMD Res 2.74K 0.1%  0.25W 1206)
R49  value 1.33K  [CR3216-1206]  (hidden comment: SMD Res 1.33K 0.1% 0.25W 1206)
R50  value 120R  Supplier Part Number 1: P120BCCT-ND  [CR3216-1206]  (hidden comment: SMD Res 120ohm 0.1% 0.25W  1206)
R53  value 10K  [CR3216-1206]  (hidden comment: 10K Resistor 1206 0.25W 0.1%)
R54  value 10K  [CR3216-1206]  (hidden comment: 10K Resistor 1206 0.25W 0.1%)
TP15  TESTPT  [TP3heater]  (value not drawn)
TP16  TESTPT  [TP3heater]  (value not drawn)
TP17  TESTPT  [TP3heater]  (value not drawn)
TP18  TESTPT  [TP3heater]  (value not drawn)
TP19  TESTPT  [TP3heater]  (value not drawn)
TP21  TESTPT  [TP3heater]  (value not drawn)
TP22  TESTPT  [TP3heater]  (value not drawn)
TP23  TESTPT  [TP3heater]  (value not drawn)
TP24  TESTPT  [TP3heater]  (value not drawn)
U11  Supplier Part Number 1: LM317TNS/NOPB-ND  [MY_TO220_HeatSink]  (hidden comment: Linear Voltage Reg + 1.25v to 37v 1.5A TO-220-3)
U12  Supplier Part Number 1: LM337TNS/NOPB-ND  [MY_TO220_HeatSink]  (hidden comment: Linear Voltage Reg -1.2v to -37v  1.5A TO-220-3)

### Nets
+15: C28.1 D7.2(A) D8.1(K) D9.1(A) R47.2 TP16.1 U11.2(Vout)
+18: C29.2 D7.1(K) R53.2 TP15.1 U11.3(Vin)
-15: C32.2 D10.2(A) D11.2(K) D12.1(K) R50.1 TP19.1 U12.3(Vout)
-18: C33.1 D12.2(A) R54.2 TP18.1 U12.2(Vin)
GND: C28.2 C29.1 C30.2 C31.1 C32.1 C33.2 D9.2(K) D11.1(A) P13.2 P14.1 R48.1 R49.2 TP17.1 TP21.1 TP22.1 TP23.1 TP24.1
NetC30_1: C30.1 D8.2(A) R47.1 R48.2 U11.1(ADJ)
NetC31_2: C31.2 D10.1(K) R49.1 R50.2 U12.1(ADJ)
NetP13_1: P13.1 R53.1
NetP14_2: P14.2 R54.1

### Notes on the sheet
- (near P15) D10 protects againts C44 (input shorts)
  D9 protects againts C43 (output shorts)
  -Vout = 1.25v ( 1 + R56 / R57 ) + R56 *(- Iadj )
  Iadj = 50E-6Amp
- D7 protects againts C40 (input shorts)
  D8 protects againts C42 (output shorts)
  Vout = 1.25v ( 1 + R55 / R54 ) + R55 * Iadj
  Iadj = 50E-6Amp
- ±18v POWER LEDS  REAR PANEL

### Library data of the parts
C28 C30-C32 = CAP_2917_10µF_50v: Manufacturers Part Number: TCJD106M050R0120; Tolerance: 5%
C29 C33 = MYCAP: as C12 on sheet OPAMP_SUM
D7 D8 D10 D12 = DIODE_S1BB: Manufacturers Part Number: S1BB-13-F; Value: S1BB-FDICT-ND
D9 D11 = DIODE RB160M-60TR: Manufacturers Part Number: RBR1MM60ATFTR; Value: RB160M-60CT-ND
P13 P14 = Header 2p 0.156inch: Manufacturers Part Number: 3-641208-2; Value: A31688-ND
P15 P16 = Mechanical Part: 2 Position Rectangular Housing Connector Receptacle Natural 0.156" (3.96mm); Manufacturers Part Number: 770849-2; Value: A24111-ND
P35-P38 = Mechanical Part: Manufacturers Part Number: 0008560105; Value: WM2305-ND
P_LED12 P_LED13 = Mechanical Part: Manufacturers Part Number: 5100H5; Value: Green 2.2v 30mA
Part8 Part9 = Mechanical Part: Manufacturers Part Number: V8508F; Value: AE10852-ND
R47 = 1206_Res_249: Manufacturers Part Number: ERA-8AEB2490V
R48 = 1206_Res_2.74K: Manufacturers Part Number: ERA-8AEB2741V
R49 = 1206_Res_1.33K: Manufacturers Part Number: ERA-8AEB1331V
R50 = 1206_Res_120R: Manufacturers Part Number: ERA-8AEB121V
R53 R54 = 1206_Res_10K: as R51 on sheet HeaterDriver
TP15-TP19 TP21-TP24 = TESTPT: as TP2 on sheet Relay
U11 = LM317: Manufacturers Part Number: LM317T/NOPB; Value: LM317TNS/NOPB-ND
U12 = LDO LM337: Manufacturers Part Number: LM337TNS/NOPB; Value: LM337TNS/NOPB-ND

## Sheet HeaterDriverCircuit.SchDoc: Heater Driver Circuit
size A; Organization: LIGO Laboratory; Address1: California Institute of Technology; Address2: Massachusetts Institute of Technology; DocumentNumber: D1600454; Revision: 3; SheetNumber: 7; SheetTotal: 8; Engineer: L.Sánchez
Used 2 times, as channels HDPRail, HDNRail. Parts and nets are listed once, with the designators drawn on the sheet.
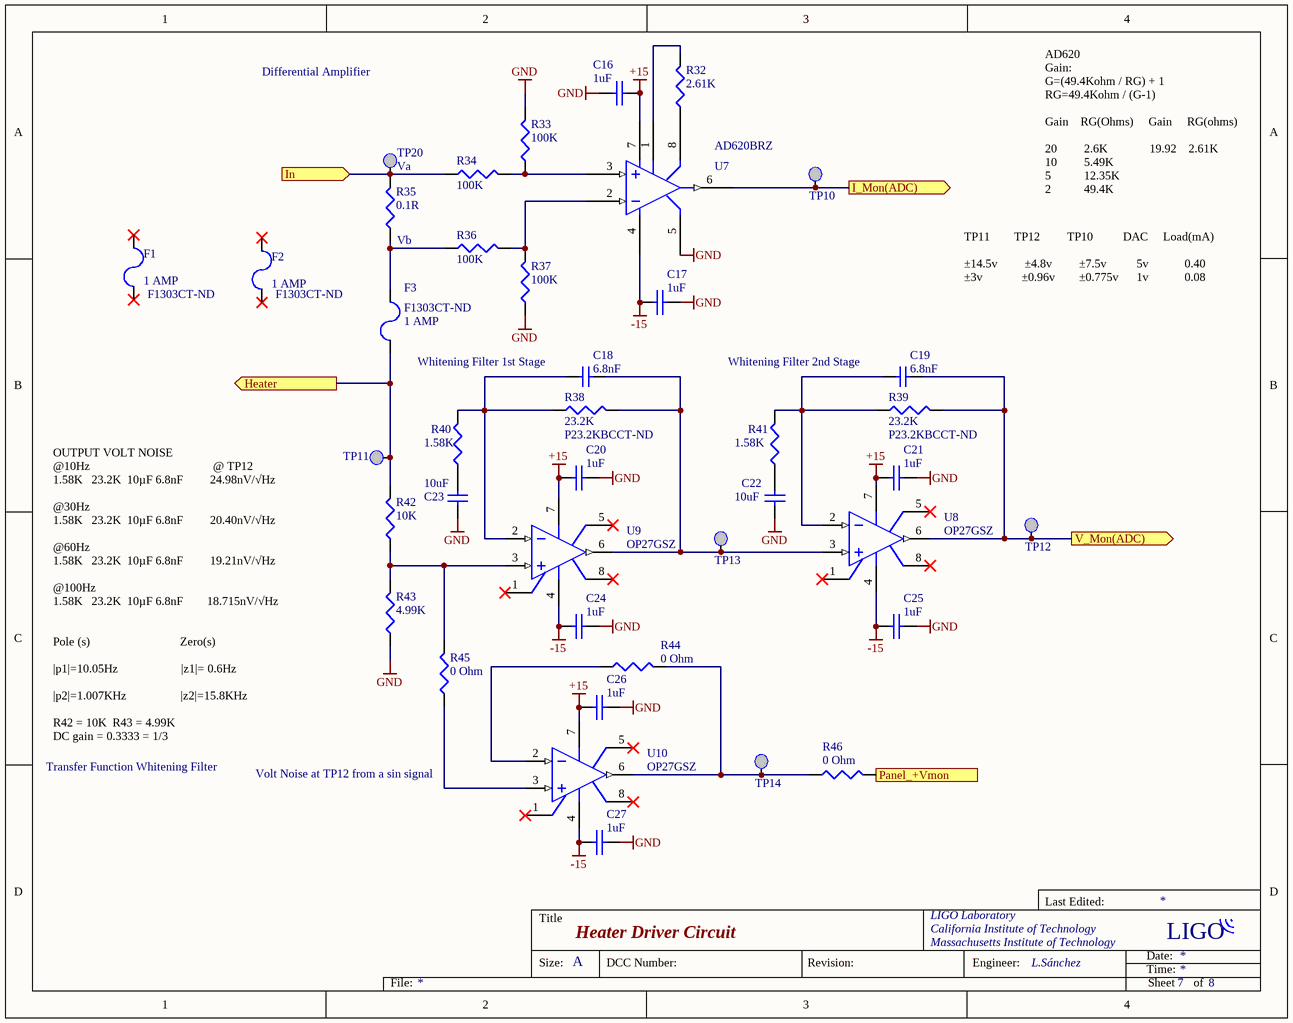
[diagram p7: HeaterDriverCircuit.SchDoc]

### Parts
C16  1uF  [CC3216-1206]
C17  1uF  [CC3216-1206]
C18  value 6.8nF  [CAP_FILM_POLY_0.197inch]  (hidden comment: Cap Film 6.8nF 100V 5% Polyester 0.197inch)
C19  value 6.8nF  [CAP_FILM_POLY_0.197inch]  (hidden comment: Cap Film 6.8nF 100V 5% Polyester 0.197inch)
C20  1uF  [CC3216-1206]
C21  1uF  [CC3216-1206]
C22  value 10uF  [CAP_FILM_0.886inch]  (hidden comment: Cap Film 10uF 100v 0.886inch)
C23  value 10uF  [CAP_FILM_0.886inch]  (hidden comment: Cap Film 10uF 100v 0.886inch)
C24  1uF  [CC3216-1206]
C25  1uF  [CC3216-1206]
C26  1uF  [CC3216-1206]
C27  1uF  [CC3216-1206]
F1  value 1 AMP  Digikey Part Number: F1303CT-ND  [SMD FUSE]  (hidden comment: FUSE BRD MNT 1A 125VAC/VDC 2SMD)
F2  value 1 AMP  Digikey Part Number: F1303CT-ND  [SMD FUSE]  (hidden comment: FUSE BRD MNT 1A 125VAC/VDC 2SMD)
F3  value 1 AMP  Digikey Part Number: F1303CT-ND  [SMD FUSE]  (hidden comment: FUSE BRD MNT 1A 125VAC/VDC 2SMD)
R32  value 2.61K  [CR3216-1206]  (hidden comment: RES SMD 2.61K OHM 0.1% 1/4W 1206)
R33  value 100K  [CR3216-1206]  (hidden comment: SMD Res 1206 100K 0.25W)
R34  value 100K  [CR3216-1206]  (hidden comment: SMD Res 1206 100K 0.25W)
R35  value 0.1R  [D2PAK_RES]  (hidden comment: RES SMD 0.1 OHM 1% 25W D2PAK)
R36  value 100K  [CR3216-1206]  (hidden comment: SMD Res 1206 100K 0.25W)
R37  value 100K  [CR3216-1206]  (hidden comment: SMD Res 1206 100K 0.25W)
R38  value 23.2K  Supplier Part Number 1: P23.2KBCCT-ND  [CR3216-1206]  (hidden comment: SMD Res 1206 23.2K 0.1% 0.25W)
R39  value 23.2K  Supplier Part Number 1: P23.2KBCCT-ND  [CR3216-1206]  (hidden comment: SMD Res 1206 23.2K 0.1% 0.25W)
R40  value 1.58K  [CR3216-1206]  (hidden comment: SMD Res 1.58K 0.1% 0.25W 1206)
R41  value 1.58K  [CR3216-1206]  (hidden comment: SMD Res 1.58K 0.1% 0.25W 1206)
R42  value 10K  [CR3216-1206]  (hidden comment: 10K Resistor 1206 0.25W 0.1%)
R43  4.99K  [CR3216-1206]
R44  0 Ohm  [CR3216-1206]
R45  0 Ohm  [CR3216-1206]
R46  0 Ohm  [CR3216-1206]
TP10  TESTPT  [TP3heater]  (value not drawn)
TP11  TESTPT  [TP3heater]  (value not drawn)
TP12  TESTPT  [TP3heater]  (value not drawn)
TP13  TESTPT  [TP3heater]  (value not drawn)
TP14  TESTPT  [TP3heater]  (value not drawn)
TP20  TESTPT  [TP3heater]  (value not drawn)
U7  AD620BRZ  [SOIC_8P_]
U8  OP27GSZ  [SO8_N]
U9  OP27GSZ  [SO8_N]
U10  OP27GSZ  [SO8_N]

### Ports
Heater (out), I_Mon(ADC) (out), In (in), Panel_+Vmon (out), V_Mon(ADC) (out)

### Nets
+15: C16.2 C20.1 C21.1 C26.1 U7.7(+Vs) U8.7(V+) U9.7(V+) U10.7(V+)
-15: C17.1 C24.1 C25.1 C27.1 U7.4(-Vs) U8.4(V-) U9.4(V-) U10.4(V-)
GND: C16.1 C17.2 C20.2 C21.2 C22.1 C23.1 C24.2 C25.2 C26.2 C27.2 R33.2 R37.1 R43.1 U7.5(REF)
Heater: F3.1 R42.2 TP11.1 ; port Heater
I_Mon(ADC): TP10.1 U7.6(OUT) ; port I_Mon(ADC)
In: R34.1 R35.3 TP20.1 ; port In
Panel_+Vmon: R46.2 ; port Panel_+Vmon
V_Mon(ADC): C19.2 R39.2 TP12.1 U8.6(OUT) ; port V_Mon(ADC)
NetC18_1: C18.1 R38.1 R40.2 U9.2(IN-)
NetC18_2: C18.2 R38.2 TP13.1 U8.3(IN+) U9.6(OUT)
NetC19_1: C19.1 R39.1 R41.2 U8.2(IN-)
NetC22_2: C22.2 R41.1
NetC23_2: C23.2 R40.1
NetF3_2: F3.2 R35.1 R36.1
NetR32_1: R32.1 U7.8(RG)
NetR32_2: R32.2 U7.1(RG*)
NetR33_1: R33.1 R34.2 U7.3(+IN)
NetR36_2: R36.2 R37.2 U7.2(-IN)
NetR42_1: R42.1 R43.2 R45.2 U9.3(IN+)
NetR44_1: R44.1 U10.2(IN-)
NetR44_2: R44.2 R46.1 TP14.1 U10.6(OUT)
NetR45_1: R45.1 U10.3(IN+)

Not connected (* = marked no-connect by the designer): F1 1* 2*; F2 1* 2*; U8 1(NULL1)* 5(NC)* 8(NULL2)*; U9 1(NULL1)* 5(NC)* 8(NULL2)*; U10 1(NULL1)* 5(NC)* 8(NULL2)*

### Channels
HDPRail: designators end in _HDPRail; ports Heater=NetF3_HDPRail_1 I_Mon(ADC)=NetR27_HDPR_I_DifferentialDriver_1 In=R Panel_+Vmon=NetP7_1 V_Mon(ADC)=NetC19_HDPRail_2
HDNRail: designators end in _HDNRail; ports Heater=NetF3_HDNRail_1 I_Mon(ADC)=NetR27_HDNR_I_DifferentialDriver_1 In=L Panel_+Vmon=NetP12_1 V_Mon(ADC)=NetC19_HDNRail_2

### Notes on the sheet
- Differential Amplifier
- (near TP20) Va
- AD620
  Gain:
  G=(49.4Kohm / RG) + 1
  RG=49.4Kohm / (G-1)
  Gain    RG(Ohms)     Gain     RG(ohms)
  20         2.6K              19.92    2.61K
  10         5.49K
  5           12.35K
  2           49.4K
- (near R35) Vb
- TP11        TP12         TP10          DAC     Load(mA)
  ±14.5v         ±4.8v         ±7.5v          5v            0.40
  ±3v             ±0.96v        ±0.775v      1v            0.08
- (near C18) Whitening Filter 1st Stage
- (near C19) Whitening Filter 2nd Stage
- Transfer Function Whitening Filter
- OUTPUT VOLT NOISE
  @10Hz                                         @ TP12
  1.58K   23.2K  10µF 6.8nF         24.98nV/√Hz
  @30Hz
  1.58K   23.2K  10µF 6.8nF         20.40nV/√Hz
  @60Hz
  1.58K   23.2K  10µF 6.8nF         19.21nV/√Hz
  @100Hz
  1.58K   23.2K  10µF 6.8nF        18.715nV/√Hz
  Pole (s)                              Zero(s)
  |p1|=10.05Hz                     |z1|= 0.6Hz
  |p2|=1.007KHz                  |z2|=15.8KHz
  R42 = 10K  R43 = 4.99K
  DC gain = 0.3333 = 1/3
- Volt Noise at TP12 from a sin signal

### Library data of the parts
C16 C17 C20 C21 C24-C27 = MYCAP: as C12 on sheet OPAMP_SUM
C18 C19 = CAP_Radial_6800pF_Polyester: Manufacturers Part Number: R82EC1680DQ50J
C22 C23 = CAP_10uF_Polyester: Cap Film 10uF 100v +-5% 0.886inch; Manufacturers Part Number: ECQ-E1106JF; Tolerance: 3%
F1-F3 = SMD FUSE 1AMP: Manufacturers Part Number: 0154001.DRT
R32 = 1206_Res_5.49K: Manufacturers Part Number: ERA-8AEB2611V
R33 R34 R36 R37 = 1206_Res_100K: Manufacturers Part Number: ERA-8AEB104V; Tolerance: 0.1%
R35 = RES_D2PAK_1R00: 'Manufacturers Part Number: PWR263S-35-1R00F; Manufacturers Part Number: PWR163S-25-R100FE; Tolerance: 0.1%
R38 R39 = 1206_Res_23.2K: Manufacturers Part Number: ERA-8AEB2322V
R40 R41 = 1206_Res_1.58K: Manufacturers Part Number: ERA-8AEB1581V
R42 = 1206_Res_10K: as R51 on sheet HeaterDriver
R43 = Res3: as R26 on sheet DifferentialDriver
R44-R46 = Res3: Resistor; Tolerance: 0.1%
TP10-TP14 TP20 = TESTPT: as TP2 on sheet Relay
U7 = AD620: Low power instrumentation amplifier; 'Manufacturers Part Number: AD620BRZ-R7; Value: AD620BRZ-R7CT-ND
U8-U10 = ADOP27AQ: as U5 on sheet OPAMP_SUM

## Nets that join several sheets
+15: HeaterDriver (R51.2), OPAMP_SUM (C12.1 U5.7), LowPassFilter (C6.1 C7.1 U3.7 U4.7), DR1 (C2_DR1.1 D1_DR1.2 D4_DR1.2 U1_DR1.4), DR2 (C2_DR2.1 D1_DR2.2 D4_DR2.2 U1_DR2.4), DR3 (C2_DR3.1 D1_DR3.2 D4_DR3.2 U1_DR3.4), HDNR_I_DifferentialDriver (C14_HDNR_I_DifferentialDriver.2 U6_HDNR_I_DifferentialDriver.8), HDNR_V_DifferentialDriver (C14_HDNR_V_DifferentialDriver.2 U6_HDNR_V_DifferentialDriver.8), Voltage Regulator (7 pins), HDPRail (8 pins), HDNRail (8 pins), DifferentialDriver (C14_DifferentialDriver.2 U6_DifferentialDriver.8), HDPR_V_DifferentialDriver (C14_HDPR_V_DifferentialDriver.2 U6_HDPR_V_DifferentialDriver.8), HDPR_I_DifferentialDriver (C14_HDPR_I_DifferentialDriver.2 U6_HDPR_I_DifferentialDriver.8)
+18: HeaterDriver (P1.1), Relay (R12.2 R18.1), Voltage Regulator (5 pins)
-15: HeaterDriver (R52.1), OPAMP_SUM (C13.1 U5.4), LowPassFilter (C10.1 C11.1 U3.4 U4.4), DR1 (C3_DR1.1 D1_DR1.1 D4_DR1.1 U1_DR1.13), DR2 (C3_DR2.1 D1_DR2.1 D4_DR2.1 U1_DR2.13), DR3 (C3_DR3.1 D1_DR3.1 D4_DR3.1 U1_DR3.13), HDNR_I_DifferentialDriver (C15_HDNR_I_DifferentialDriver.2 U6_HDNR_I_DifferentialDriver.4), HDNR_V_DifferentialDriver (C15_HDNR_V_DifferentialDriver.2 U6_HDNR_V_DifferentialDriver.4), Voltage Regulator (7 pins), HDPRail (8 pins), HDNRail (8 pins), DifferentialDriver (C15_DifferentialDriver.2 U6_DifferentialDriver.4), HDPR_V_DifferentialDriver (C15_HDPR_V_DifferentialDriver.2 U6_HDPR_V_DifferentialDriver.4), HDPR_I_DifferentialDriver (C15_HDPR_I_DifferentialDriver.2 U6_HDPR_I_DifferentialDriver.4)
-18: HeaterDriver (P1.3), Voltage Regulator (5 pins)
GND: HeaterDriver (13 pins), Relay (R14.1 R15.2 U2.2), OPAMP_SUM (C12.2 C13.2 U5.3), LowPassFilter (6 pins), DR1 (6 pins), DR2 (6 pins), DR3 (6 pins), HDNR_I_DifferentialDriver (C14_HDNR_I_DifferentialDriver.1 C15_HDNR_I_DifferentialDriver.1 U6_HDNR_I_DifferentialDriver.5), HDNR_V_DifferentialDriver (C14_HDNR_V_DifferentialDriver.1 C15_HDNR_V_DifferentialDriver.1 U6_HDNR_V_DifferentialDriver.5), Voltage Regulator (17 pins), HDPRail (14 pins), HDNRail (14 pins), DifferentialDriver (C14_DifferentialDriver.1 C15_DifferentialDriver.1 U6_DifferentialDriver.5), HDPR_V_DifferentialDriver (C14_HDPR_V_DifferentialDriver.1 C15_HDPR_V_DifferentialDriver.1 U6_HDPR_V_DifferentialDriver.5), HDPR_I_DifferentialDriver (C14_HDPR_I_DifferentialDriver.1 C15_HDPR_I_DifferentialDriver.1 U6_HDPR_I_DifferentialDriver.5)
L: HeaterDriver (P11.3), HDNRail (R34_HDNRail.1 R35_HDNRail.3 TP20_HDNRail.1)
NetC5_1: OPAMP_SUM (R25.1), LowPassFilter (C5.1 TP6.1 U4.2 U4.6)
NetC19_HDNRail_2: HDNR_V_DifferentialDriver (R27_HDNR_V_DifferentialDriver.1 R30_HDNR_V_DifferentialDriver.1 U6_HDNR_V_DifferentialDriver.3), HDNRail (C19_HDNRail.2 R39_HDNRail.2 TP12_HDNRail.1 U8_HDNRail.6)
NetC19_HDPRail_2: HDPRail (C19_HDPRail.2 R39_HDPRail.2 TP12_HDPRail.1 U8_HDPRail.6), HDPR_V_DifferentialDriver (R27_HDPR_V_DifferentialDriver.1 R30_HDPR_V_DifferentialDriver.1 U6_HDPR_V_DifferentialDriver.3)
NetF3_HDNRail_1: HeaterDriver (P8.4), HDNRail (F3_HDNRail.1 R42_HDNRail.2 TP11_HDNRail.1)
NetF3_HDPRail_1: HeaterDriver (P8.1), HDPRail (F3_HDPRail.1 R42_HDPRail.2 TP11_HDPRail.1)
NetH1_1: Relay (H1.1), DR2 (R9_DR2.1 TP1_DR2.1 U1_DR2.10)
NetJ1_1: HeaterDriver (J1.1), DR1 (R2_DR1.2 R4_DR1.2)
NetJ1_2: HeaterDriver (J1.2), DR2 (R2_DR2.2 R4_DR2.2)
NetJ1_3: HeaterDriver (J1.3), DR3 (R2_DR3.2 R4_DR3.2)
NetJ1_6: HeaterDriver (J1.6), DR1 (R7_DR1.2 R10_DR1.1)
NetJ1_7: HeaterDriver (J1.7), DR2 (R7_DR2.2 R10_DR2.1)
NetJ1_8: HeaterDriver (J1.8), DR3 (R7_DR3.2 R10_DR3.1)
NetJ4_1: HeaterDriver (J4.1), HDPR_V_DifferentialDriver (R28_HDPR_V_DifferentialDriver.2)
NetJ4_2: HeaterDriver (J4.2), HDPR_I_DifferentialDriver (R28_HDPR_I_DifferentialDriver.2)
NetJ4_3: HeaterDriver (J4.3), HDNR_V_DifferentialDriver (R28_HDNR_V_DifferentialDriver.2)
NetJ4_4: HeaterDriver (J4.4), HDNR_I_DifferentialDriver (R28_HDNR_I_DifferentialDriver.2)
NetJ4_6: HeaterDriver (J4.6), HDPR_V_DifferentialDriver (R31_HDPR_V_DifferentialDriver.2)
NetJ4_7: HeaterDriver (J4.7), HDPR_I_DifferentialDriver (R31_HDPR_I_DifferentialDriver.2)
NetJ4_8: HeaterDriver (J4.8), HDNR_V_DifferentialDriver (R31_HDNR_V_DifferentialDriver.2)
NetJ4_9: HeaterDriver (J4.9), HDNR_I_DifferentialDriver (R31_HDNR_I_DifferentialDriver.2)
NetP7_1: HeaterDriver (P7.1), HDPRail (R46_HDPRail.2)
NetP12_1: HeaterDriver (P12.1), HDNRail (R46_HDNRail.2)
NetR9_DR1_1: Relay (R13.4 R13.5 TP2.1), DR1 (R9_DR1.1 TP1_DR1.1 U1_DR1.10)
NetR9_DR3_1: LowPassFilter (R19.2), DR3 (R9_DR3.1 TP1_DR3.1 U1_DR3.10)
NetR16_1: Relay (R16.1), OPAMP_SUM (R24.1)
NetR23_2: OPAMP_SUM (R23.2 TP7.1 U5.6), DifferentialDriver (R27_DifferentialDriver.1 R30_DifferentialDriver.1 U6_DifferentialDriver.3)
NetR27_HDNR_I_DifferentialDriver_1: HDNR_I_DifferentialDriver (R27_HDNR_I_DifferentialDriver.1 R30_HDNR_I_DifferentialDriver.1 U6_HDNR_I_DifferentialDriver.3), HDNRail (TP10_HDNRail.1 U7_HDNRail.6)
NetR27_HDPR_I_DifferentialDriver_1: HDPRail (TP10_HDPRail.1 U7_HDPRail.6), HDPR_I_DifferentialDriver (R27_HDPR_I_DifferentialDriver.1 R30_HDPR_I_DifferentialDriver.1 U6_HDPR_I_DifferentialDriver.3)
OUTN: HeaterDriver (P6.3), DifferentialDriver (R31_DifferentialDriver.2)
OUTP: HeaterDriver (P6.1), DifferentialDriver (R28_DifferentialDriver.2)
R: HeaterDriver (P11.1), HDPRail (R34_HDPRail.1 R35_HDPRail.3 TP20_HDPRail.1)

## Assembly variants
BRS: not fitted R6_DR1 R6_DR2 R6_DR3
SR3: not fitted R6_DR1 R6_DR2 R6_DR3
